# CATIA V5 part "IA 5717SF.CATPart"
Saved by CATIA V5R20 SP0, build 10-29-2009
Part number: IA 5717SF
Revision: ANY
Definition: UNKNOWN
Nomenclature: IA 5717SF
Source: Unknown
Bounding box of the stored display mesh (mm): x -2.85 to 2.85, y -7.925 to 9.045, z -2.711 to 2.711
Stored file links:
  C:\Users\Utente\Desktop\IO LAVORO\3D X SITO CF\CUMSA\3D files FA\FA 1057SF\IA 5717SF.CATPart

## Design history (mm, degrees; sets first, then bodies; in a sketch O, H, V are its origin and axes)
Body1 "Cortar-Extruir2" (main body)
  Solid1: solid without history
